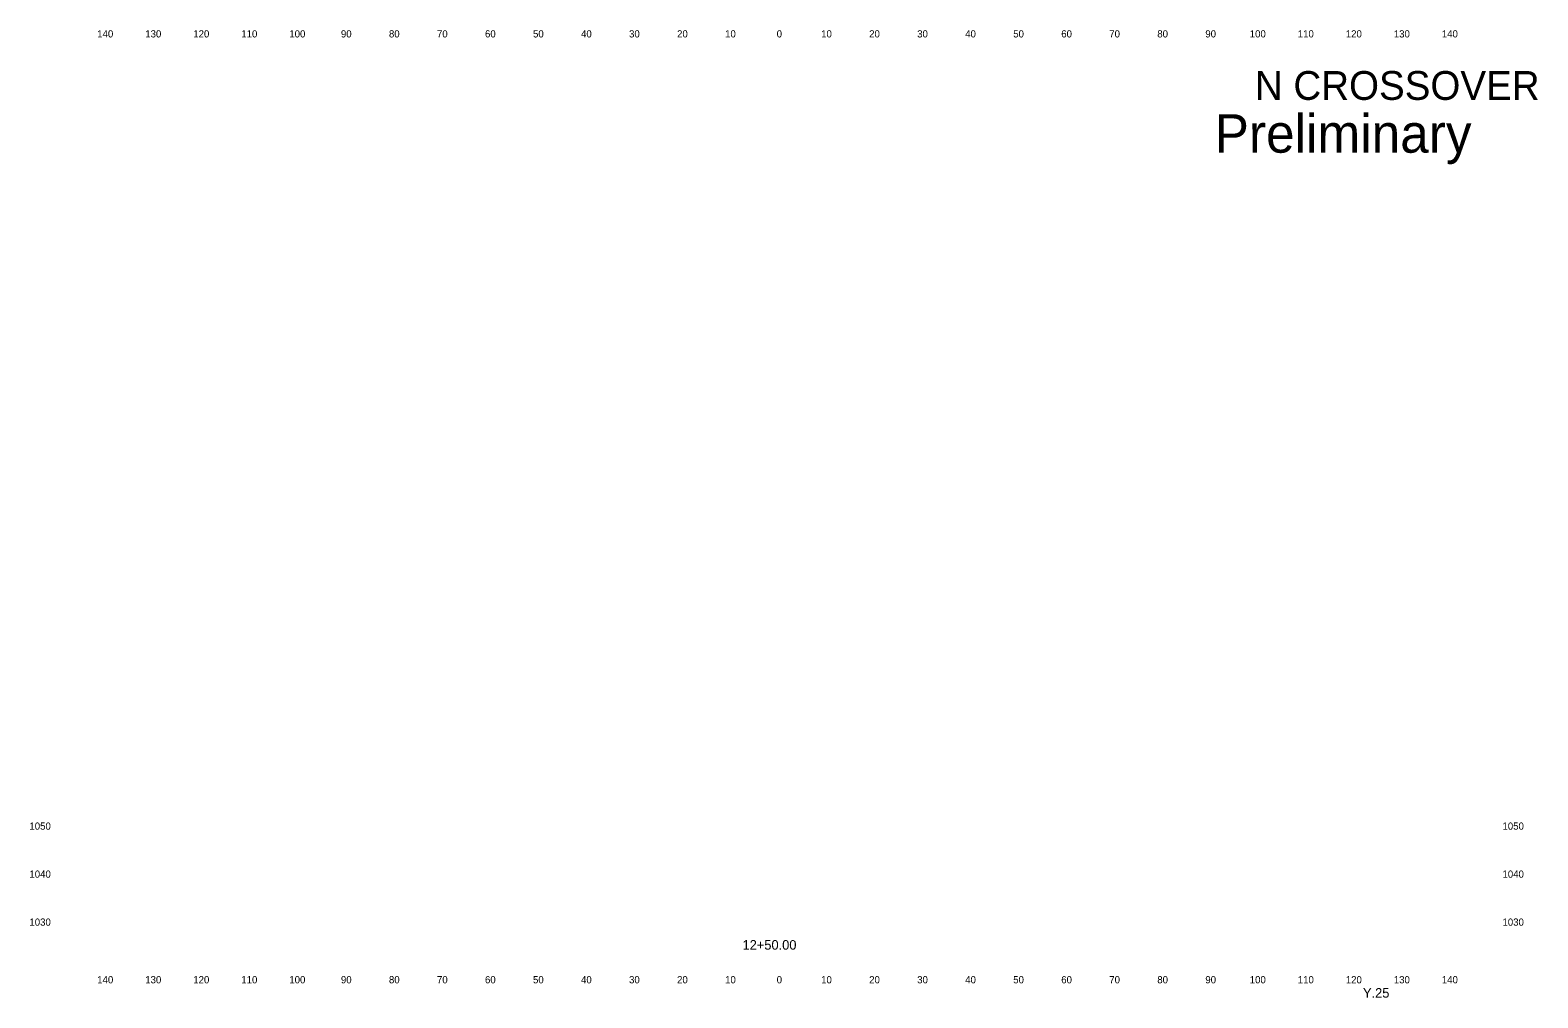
# Model space of a CAD drawing. Extents: x 10123 to 14767, y 9730 to 9950.
# Drawn here: x 14453.3 to 14767.3, y 9739 to 9940.5 of the extents above; entities that cross this region are included whole.
import ezdxf

# ---------------------------------------------------------------- set-up
doc = ezdxf.new("R2010")
doc.units = 0
for name, color, linetype in [('dsnTextCpn', 7, 'Continuous'), ('dsnTextCpnTitleSheetLocDesc', 7, 'Continuous'), ('dsnTextCpnTitleSheetPIN', 7, 'Continuous')]:
    doc.layers.add(name, color=color, linetype=linetype)

msp = doc.modelspace()

# ---------------------------------------------------------------- texts
at = {"layer": 'dsnTextCpn'}
for s, height, p in [('140', 1.5, (14467.27, 9939)), ('130', 1.5, (14477.27, 9939)), ('120', 1.5, (14487.27, 9939)), ('110', 1.5, (14497.27, 9939)), ('100', 1.5, (14507.27, 9939)), ('90', 1.5, (14518.02, 9939)), ('80', 1.5, (14528.02, 9939)), ('70', 1.5, (14538.02, 9939)), ('60', 1.5, (14548.02, 9939)), ('50', 1.5, (14558.02, 9939)), ('40', 1.5, (14568.02, 9939)), ('30', 1.5, (14578.02, 9939)), ('20', 1.5, (14588.02, 9939)), ('10', 1.5, (14598.02, 9939)), ('0', 1.5, (14608.76, 9939)), ('0', 1.5, (14608.76, 9939)), ('10', 1.5, (14618.02, 9939)), ('20', 1.5, (14628.02, 9939)), ('30', 1.5, (14638.02, 9939)), ('40', 1.5, (14648.02, 9939)), ('50', 1.5, (14658.02, 9939)), ('60', 1.5, (14668.02, 9939)), ('70', 1.5, (14678.02, 9939)), ('80', 1.5, (14688.02, 9939)), ('90', 1.5, (14698.02, 9939)), ('100', 1.5, (14707.27, 9939)), ('110', 1.5, (14717.27, 9939)), ('120', 1.5, (14727.27, 9939)), ('130', 1.5, (14737.27, 9939)), ('140', 1.5, (14747.27, 9939)), ('N CROSSOVER', 6, (14708.34, 9926)), ('1050', 1.5, (14453.15, 9774)), ('1050', 1.5, (14759.9, 9774)), ('1040', 1.5, (14453.15, 9764)), ('1040', 1.5, (14759.9, 9764)), ('1030', 1.5, (14453.15, 9754)), ('1030', 1.5, (14759.9, 9754)), ('12+50.00', 2, (14601.65, 9749)), ('140', 1.5, (14467.27, 9742)), ('130', 1.5, (14477.27, 9742)), ('120', 1.5, (14487.27, 9742)), ('110', 1.5, (14497.27, 9742)), ('100', 1.5, (14507.27, 9742)), ('90', 1.5, (14518.02, 9742)), ('80', 1.5, (14528.02, 9742)), ('70', 1.5, (14538.02, 9742)), ('60', 1.5, (14548.02, 9742)), ('50', 1.5, (14558.02, 9742)), ('40', 1.5, (14568.02, 9742)), ('30', 1.5, (14578.02, 9742)), ('20', 1.5, (14588.02, 9742)), ('10', 1.5, (14598.02, 9742)), ('0', 1.5, (14608.76, 9742)), ('0', 1.5, (14608.76, 9742)), ('10', 1.5, (14618.02, 9742)), ('20', 1.5, (14628.02, 9742)), ('30', 1.5, (14638.02, 9742)), ('40', 1.5, (14648.02, 9742)), ('50', 1.5, (14658.02, 9742)), ('60', 1.5, (14668.02, 9742)), ('70', 1.5, (14678.02, 9742)), ('80', 1.5, (14688.02, 9742)), ('90', 1.5, (14698.02, 9742)), ('100', 1.5, (14707.27, 9742)), ('110', 1.5, (14717.27, 9742)), ('120', 1.5, (14727.27, 9742)), ('130', 1.5, (14737.27, 9742)), ('140', 1.5, (14747.27, 9742))]:
    msp.add_text(s, height=height, dxfattribs=at).set_placement(p)
at = {"layer": 'dsnTextCpnTitleSheetLocDesc'}
msp.add_text('Preliminary', height=8, dxfattribs=at).set_placement((14699.97, 9915))
at = {"layer": 'dsnTextCpnTitleSheetPIN'}
msp.add_text('Y.25', height=2, dxfattribs=at).set_placement((14730.85, 9739))

doc.saveas('drawing.dxf')
